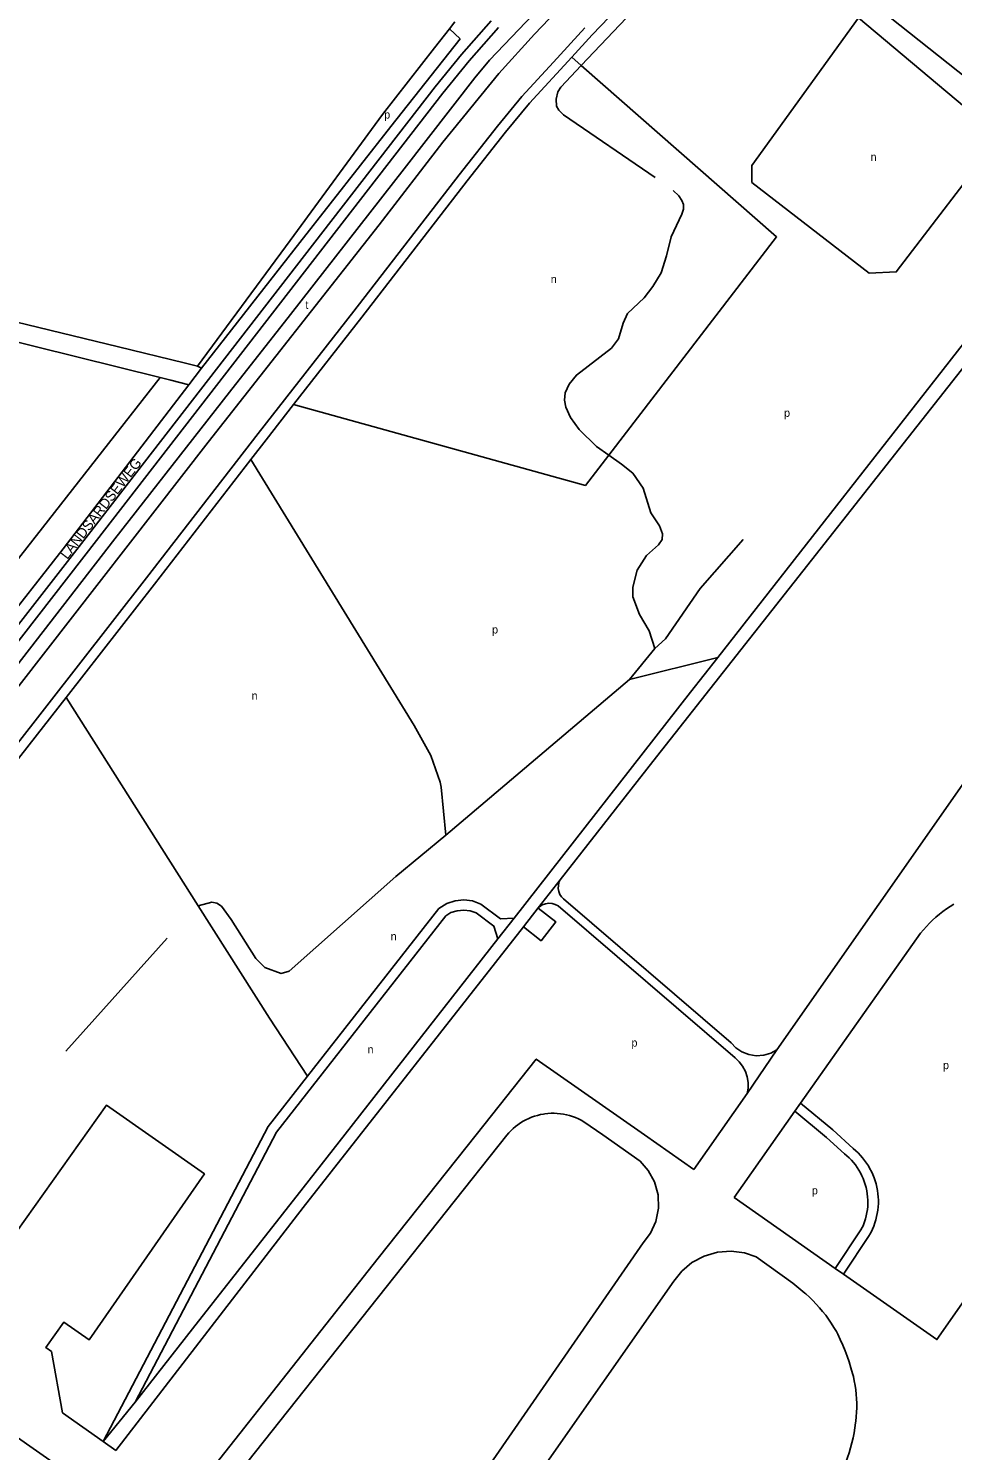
# Model space of a CAD drawing. Extents: x 153608 to 155459, y 385052 to 386919.
# Drawn here: x 154363 to 154825, y 385542 to 386253 of the extents above; entities that cross this region are included whole.
import ezdxf

# ---------------------------------------------------------------- set-up
doc = ezdxf.new("R2010")
doc.units = 0
for name, color, linetype in [('BLT_Basislijn', 7, 'Continuous'), ('BLT_Centroide', 7, 'Continuous'), ('BLT_Gemeentegrens', 7, 'Continuous'), ('BLT_Straatnaam', 7, 'Continuous'), ('BLT_Vlakafsluiter', 7, 'Continuous')]:
    doc.layers.add(name, color=color, linetype=linetype)

msp = doc.modelspace()

# ---------------------------------------------------------------- linework, layer by layer
at = {"layer": 'BLT_Basislijn'}
for p, q in [((154573.02, 386252.97), (154578.48, 386248.02)), ((154638.96, 386234.72), (154634.18, 386238.92)), ((154674.74, 385886.78), (154837.72, 386093.56)), ((154343.74, 385970.46), (154428.43, 386078.64)), ((154428.43, 386078.64), (154433.8, 386077.3)), ((154433.8, 386077.3), (154442.81, 386075.07)), ((154380, 385993.06), (154333.96, 385934.36)), ((154663.15, 385927.63), (154675.74, 385943.15)), ((154663.15, 385927.63), (154707.16, 385938.62)), ((154693.63, 385921.31), (154707.16, 385938.62)), ((154571.22, 385849.81), (154663.15, 385927.63)), ((154605.36, 385808.4), (154693.63, 385921.31)), ((154381.51, 385918.75), (154447.56, 385814.53)), ((154628.36, 385827.58), (154674.74, 385886.78)), ((154617.38, 385813.47), (154628.36, 385827.58)), ((154715.87, 385738.47), (154627.35, 385814.5)), ((154713.81, 385746.01), (154630.12, 385817.98)), ((154610.04, 385804.1), (154617.38, 385813.47)), ((154617.44, 385813.43), (154617.38, 385813.47)), ((154500, 385663.66), (154610.04, 385804.1)), ((154808.52, 385800.91), (154748.61, 385715.92)), ((154431.99, 385798.35), (154381.41, 385741.83)), ((154520.98, 385700.47), (154597.23, 385798.01)), ((154736.7, 385742.49), (154721.86, 385720.64)), ((154721.86, 385720.64), (154695.27, 385682.74)), ((154748.61, 385715.92), (154745.72, 385711.82)), ((154748.61, 385715.92), (154764.75, 385702.49)), ((154745.72, 385711.82), (154715.32, 385668.7)), ((154745.72, 385711.82), (154761.55, 385698.65)), ((154774.87, 385693.18), (154764.75, 385702.49)), ((154500, 385673.64), (154520.98, 385700.47)), ((154541.49, 385623.9), (154601.84, 385699.97)), ((154770.53, 385690.61), (154761.55, 385698.65)), ((154765.91, 385633.26), (154715.32, 385668.7)), ((154406.39, 385542.21), (154500, 385663.66)), ((154778.73, 385652.5), (154765.91, 385633.26)), ((154780, 385654.96), (154778.73, 385652.5)), ((154669.97, 385645.98), (154558.38, 385484.76)), ((154782.89, 385649.72), (154770, 385630.39)), ((154537.42, 385638.43), (154441.78, 385517.22)), ((154770, 385630.39), (154765.91, 385633.26)), ((154685.3, 385626.86), (154450.13, 385291.98)), ((154541.49, 385623.9), (154451.39, 385510.44)), ((154406.39, 385542.21), (154399.99, 385546.73))]:
    msp.add_line(p, q, dxfattribs=at)
for points in [[(155118.98, 386516.32), (155043.31, 386507.56), (154984.44, 386500.69), (154957.8, 386497.87), (154935.67, 386494.66), (154921.56, 386492.19), (154909.21, 386489.15), (154900.34, 386486.13), (154887.57, 386481.19), (154872.57, 386474.02), (154860.57, 386467.01), (154848.91, 386458.9), (154837.63, 386449.86), (154823.59, 386436.18), (154773.02, 386383.56), (154708.26, 386316.53), (154644.42, 386250.05)], [(154638.96, 386234.72), (154832.16, 386438.21), (154847.77, 386451.8), (154859, 386460.09), (154874.32, 386469.26), (154889.64, 386476.88), (154906.27, 386482.72), (154923.43, 386487.36), (154945.45, 386491.33), (154963.11, 386493.79), (155009.53, 386499.23)], [(154745.51, 386395.94), (154651.35, 386298.5), (154593.06, 386237.32), (154585.71, 386228.52), (154550.39, 386183.09), (154493.67, 386110.22), (154463.08, 386071.36), (154405.83, 385998.1), (154327.19, 385896.61), (154289.38, 385847.11), (154273.88, 385824), (154259.18, 385798.01), (154218.87, 385726.19), (154202.46, 385696.25), (154159, 385622.99), (154144.16, 385603.56), (154139.31, 385598.7), (154138.16, 385595.98)], [(154754.37, 386395.71), (154615.6, 386250.29), (154597.76, 386230.66), (154569.71, 386196.31), (154538.03, 386154.95), (154452.53, 386046.43), (154357.94, 385924.71), (154293.71, 385841.85), (154282.27, 385823.81), (154269.07, 385801.81), (154202.93, 385683.02), (154166.56, 385620.26), (154155.85, 385605), (154148.23, 385596.21), (154143.53, 385591.51), (154141.05, 385591.43)], [(154341.17, 385934.15), (154392.73, 386000.27), (154500.64, 386139.76), (154565.87, 386224.01), (154579.08, 386240.21), (154593.88, 386257.02)], [(154640.74, 386253.44), (154625.05, 386236.37), (154609.33, 386219.18), (154597.17, 386204.41), (154577.98, 386180.02), (154525.27, 386111.88), (154477.44, 386050.65), (154421.65, 385978.46), (154354.9, 385892.7), (154310.03, 385834.83), (154295.19, 385813.79), (154283.1, 385794.92), (154259.28, 385752.24)], [(154597.57, 386253.65), (154582.89, 386236.98), (154569.79, 386220.89), (154504.59, 386136.7), (154396.67, 385997.21), (154345.11, 385931.07)], [(154578.48, 386248.02), (154543.86, 386204.2), (154498.24, 386146.17)], [(154644.42, 386250.05), (154634.18, 386238.92)], [(154634.18, 386238.92), (154613.1, 386215.91), (154601.06, 386201.28), (154581.92, 386176.95), (154529.22, 386108.82), (154495.11, 386065.15)], [(154675.94, 386178.69), (154630.03, 386209.94), (154627.74, 386212.34), (154626.64, 386214.42), (154626.35, 386217.82), (154627.23, 386221.57), (154628.71, 386223.92), (154638.96, 386234.72)], [(154652.72, 386039.91), (154736.56, 386149), (154638.96, 386234.72)], [(154060.93, 386169.83), (154073.68, 386166.67), (154428.43, 386078.64)], [(154652.72, 386039.91), (154646.62, 386044.25), (154637.92, 386052.75), (154633.65, 386058.74), (154631.19, 386063.81), (154630.56, 386067.39), (154630.92, 386071), (154632.99, 386075.31), (154636.57, 386079.89), (154654, 386093.3), (154657.53, 386097.95), (154659.84, 386105.92), (154662.07, 386110.75), (154670.46, 386118.5), (154674.81, 386124.16), (154678.94, 386131.05), (154681.52, 386139.5), (154683.87, 386149.01), (154689.19, 386160.29), (154689.98, 386162.89), (154690.06, 386165.11), (154689.23, 386167.18), (154687.7, 386169.56), (154684.83, 386172.21)], [(154707.16, 385938.62), (154835.97, 386103.38), (154838.35, 386105.66), (154840.9, 386108.05), (154844.93, 386110.45), (154847.62, 386111.79), (154850.16, 386113.89), (154852.4, 386116.73), (154853.9, 386120.32), (154854.2, 386123.31), (154854.2, 386127.49), (154853.15, 386134.07), (154852.4, 386140.21), (154851.96, 386144.84), (154851.81, 386148.88), (154851.96, 386152.17), (154852.7, 386156.36), (154854.35, 386160.54), (154856.63, 386164.91)], [(154498.24, 386146.17), (154449.15, 386083.43)], [(154449.15, 386083.43), (154447.21, 386084.35)], [(154442.81, 386075.07), (154380, 385993.06)], [(154495.11, 386065.15), (154481.39, 386047.58), (154473.79, 386037.75)], [(154495.11, 386065.15), (154641.03, 386024.7), (154652.72, 386039.91)], [(154473.79, 386037.75), (154425.6, 385975.39), (154381.51, 385918.75)], [(154473.79, 386037.75), (154555.51, 385904.76), (154563.8, 385889.74), (154568.46, 385876.32), (154568.88, 385873.95), (154571.22, 385849.81)], [(154675.74, 385943.15), (154672.89, 385952.08), (154668.14, 385960.16), (154664.73, 385969.03), (154664.75, 385973.89), (154666.93, 385982.32), (154671.5, 385989.74), (154677.64, 385995.01), (154679.35, 385997.75), (154679.55, 386000.53), (154678.01, 386004.56), (154673.77, 386011.09), (154669.86, 386023.4), (154664.73, 386030.84), (154659.05, 386035.42), (154652.72, 386039.91)], [(154675.74, 385943.15), (154681.13, 385948.03), (154698.37, 385973.2), (154719.87, 385997.69)], [(154381.51, 385918.75), (154358.84, 385889.63), (154314.05, 385831.86), (154299.34, 385811), (154287.39, 385792.35), (154263.62, 385749.77)], [(154840.32, 385887.12), (154838.7, 385888.27), (154736.7, 385742.49)], [(154571.22, 385849.81), (154546.25, 385829.28), (154492.88, 385781.87), (154488.91, 385780.74), (154480.81, 385783.67), (154476.25, 385788.21), (154463.92, 385807.76), (154459.06, 385814.45), (154456.87, 385815.92), (154454.29, 385816.41), (154447.56, 385814.53)], [(154628.36, 385827.58), (154627.81, 385826.26), (154627.51, 385824.79), (154627.48, 385823.25), (154627.76, 385821.72), (154628.33, 385820.29), (154629.14, 385819.02), (154630.12, 385817.98)], [(154447.56, 385814.53), (154483.1, 385758.46), (154502.13, 385729.32)], [(154502.13, 385729.32), (154567.84, 385813.22), (154571.69, 385815.75), (154575.93, 385817.05), (154580.24, 385817.47), (154584.63, 385817.02), (154588.84, 385815.41), (154598.66, 385808.11), (154605.36, 385808.4)], [(154627.35, 385814.5), (154626, 385815.24), (154624.44, 385815.71), (154622.76, 385815.84), (154621.08, 385815.6), (154619.5, 385815.01), (154618.14, 385814.12), (154617.44, 385813.43)], [(154808.52, 385800.91), (154809.95, 385802.61), (154811.44, 385804.27), (154812.98, 385805.86), (154814.58, 385807.41), (154816.24, 385808.89), (154817.95, 385810.31), (154819.71, 385811.67), (154821.51, 385812.97), (154823.36, 385814.2), (154825.26, 385815.36)], [(154415.94, 385566.41), (154486.65, 385701.44), (154571.27, 385809.49), (154573.83, 385811.18), (154576.92, 385812.12), (154580.23, 385812.45), (154583.46, 385812.11), (154586.41, 385810.99), (154595.25, 385804.41), (154597.23, 385798.01)], [(154610.04, 385804.1), (154618.89, 385797.11), (154626.28, 385806.5), (154617.44, 385813.43)], [(154736.7, 385742.49), (154733.68, 385740.87), (154730.2, 385739.85), (154726.46, 385739.59), (154722.7, 385740.17), (154719.21, 385741.55), (154716.2, 385743.56), (154713.81, 385746.01)], [(154695.27, 385682.74), (154670.64, 385700), (154616.5, 385737.89), (154586.45, 385700), (154537.42, 385638.43)], [(154715.87, 385738.47), (154717.88, 385736.6), (154719.61, 385734.36), (154720.98, 385731.8), (154721.91, 385729.04), (154722.36, 385726.18), (154722.33, 385723.34), (154721.86, 385720.64)], [(154399.99, 385546.73), (154482.43, 385704.16), (154502.13, 385729.32)], [(154399.99, 385546.73), (154379.63, 385561.1), (154374.24, 385591.68), (154371.37, 385593.71), (154380.3, 385606.38), (154392.94, 385597.52), (154450.59, 385680.49), (154401.66, 385714.83), (154343.04, 385632.56), (154355.71, 385623.64), (154346.8, 385610.92), (154282.5, 385655.99), (154251.78, 385650.69), (154235.63, 385661.35), (154222.76, 385642.9), (154386.19, 385528.38)], [(154901.88, 385719.14), (154900, 385716.45), (154888.39, 385700), (154816.71, 385597.68), (154770, 385630.39)], [(154620.09, 385710.46), (154618.57, 385710.17), (154617.06, 385709.8), (154615.58, 385709.35), (154614.12, 385708.83), (154612.69, 385708.23), (154611.29, 385707.55), (154609.93, 385706.81), (154608.61, 385706), (154607.33, 385705.12), (154606.1, 385704.18), (154604.92, 385703.17), (154603.79, 385702.1), (154602.72, 385700.98), (154601.84, 385699.97)], [(154640.31, 385706.63), (154638.95, 385707.39), (154637.54, 385708.07), (154636.1, 385708.68), (154634.64, 385709.22), (154633.14, 385709.69), (154631.63, 385710.07), (154630.1, 385710.38), (154628.55, 385710.61), (154627, 385710.76), (154625.43, 385710.83), (154623.87, 385710.82), (154622.31, 385710.73), (154620.76, 385710.56), (154620.09, 385710.46)], [(154640.31, 385706.63), (154649.73, 385700), (154668.41, 385686.85)], [(154668.41, 385686.85), (154672.41, 385682.28), (154675.51, 385676.62), (154677.33, 385670.14), (154677.59, 385663.32), (154676.27, 385656.72), (154673.61, 385650.83), (154669.97, 385645.98)], [(154770.53, 385690.61), (154771.74, 385689.6), (154772.89, 385688.53), (154773.99, 385687.4), (154775.02, 385686.22), (154776, 385684.98), (154776.91, 385683.7), (154777.76, 385682.37), (154778.54, 385681), (154779.24, 385679.6), (154779.88, 385678.16), (154780.43, 385676.69), (154780.92, 385675.19), (154781.33, 385673.67), (154781.66, 385672.13), (154781.91, 385670.58), (154782.08, 385669.01), (154782.18, 385667.44), (154782.19, 385665.87), (154782.12, 385664.29), (154781.97, 385662.73), (154781.75, 385661.17), (154781.44, 385659.62), (154781.06, 385658.1), (154780.6, 385656.59), (154780.06, 385655.11), (154780, 385654.96)], [(154774.87, 385693.18), (154776.12, 385692.12), (154777.33, 385690.99), (154778.47, 385689.8), (154779.56, 385688.57), (154780.59, 385687.28), (154781.55, 385685.94), (154782.45, 385684.55), (154783.27, 385683.13), (154784.03, 385681.66), (154784.72, 385680.16), (154785.33, 385678.63), (154785.87, 385677.08), (154786.33, 385675.49), (154786.71, 385673.89), (154787.02, 385672.27), (154787.25, 385670.64), (154787.4, 385668.99), (154787.46, 385667.35), (154787.45, 385665.7), (154787.36, 385664.05), (154787.19, 385662.41), (154786.94, 385660.78), (154786.61, 385659.17), (154786.2, 385657.57), (154785.72, 385655.99), (154785.15, 385654.44), (154784.52, 385652.92), (154783.81, 385651.43), (154783.03, 385649.98), (154782.89, 385649.72)], [(154415.94, 385566.41), (154444.68, 385603.1), (154500, 385673.64)], [(154726.46, 385638.98), (154720.49, 385641.04), (154713.88, 385641.92), (154707.01, 385641.41), (154700.33, 385639.44), (154694.28, 385636.15), (154689.21, 385631.83), (154685.3, 385626.86)], [(154750.73, 385620.95), (154744.69, 385625.91), (154726.46, 385638.98)], [(154766.51, 385601.68), (154765.27, 385603.78), (154763.95, 385605.84), (154762.58, 385607.86), (154761.13, 385609.82), (154759.62, 385611.74), (154758.05, 385613.61), (154756.42, 385615.43), (154754.73, 385617.19), (154752.99, 385618.9), (154751.19, 385620.55), (154750.73, 385620.95)], [(154774.58, 385580.76), (154773.75, 385583.64), (154772.84, 385586.49), (154771.85, 385589.32), (154770.79, 385592.13), (154769.66, 385594.9), (154768.45, 385597.65), (154767.17, 385600.36), (154766.51, 385601.68)], [(154776.15, 385556.86), (154776.39, 385559.1), (154776.55, 385561.35), (154776.63, 385563.6), (154776.63, 385565.85), (154776.55, 385568.1), (154776.39, 385570.34), (154776.15, 385572.58), (154775.83, 385574.81), (154775.44, 385577.02), (154774.96, 385579.22), (154774.58, 385580.76)], [(154770.17, 385533.93), (154771.13, 385536.3), (154772.02, 385538.7), (154772.83, 385541.13), (154773.57, 385543.58), (154774.22, 385546.06), (154774.8, 385548.55), (154775.3, 385551.06), (154775.73, 385553.58), (154776.07, 385556.12), (154776.15, 385556.86)]]:
    msp.add_lwpolyline(points, dxfattribs=at)
for points in [[(154856.58, 386359.27), (154783.71, 386266.32), (154856.11, 386208.79), (154924.13, 386301.7)], [(154777.49, 386258.49), (154724.3, 386184.63), (154724.27, 386176.18), (154782.89, 386130.91), (154796.43, 386131.44), (154848.23, 386199.21)]]:
    msp.add_lwpolyline(points, close=True, dxfattribs=at)
at = {"layer": 'BLT_Gemeentegrens'}
for p, q in [((154573.02, 386252.97), (154575.73, 386256.44)), ((154440.56, 386085.97), (154447.21, 386084.35))]:
    msp.add_line(p, q, dxfattribs=at)
for points in [[(154539.69, 386210.13), (154565.65, 386243.49), (154573.02, 386252.97)], [(154447.21, 386084.35), (154493.45, 386147.24), (154539.69, 386210.13)], [(154281.95, 386124.59), (154407.66, 386093.98), (154440.56, 386085.97)]]:
    msp.add_lwpolyline(points, dxfattribs=at)
at = {"layer": 'BLT_Vlakafsluiter'}
for p, q in [((154442.81, 386075.07), (154449.15, 386083.43)), ((154597.23, 385798.01), (154605.36, 385808.4)), ((154399.99, 385546.73), (154415.94, 385566.41))]:
    msp.add_line(p, q, dxfattribs=at)

# ---------------------------------------------------------------- texts
at = {"layer": 'BLT_Centroide'}
for s, p in [('p', (154540.46, 386208.14)), ('n', (154783.58, 386186.97)), ('n', (154623.72, 386125.89)), ('t', (154501.07, 386113.02)), ('p', (154740.34, 386059.03)), ('p', (154594.4, 385950.69)), ('n', (154474.16, 385917.64)), ('n', (154543.71, 385797.32)), ('n', (154532.13, 385740.78)), ('p', (154664.06, 385744.17)), ('p', (154819.79, 385732.9)), ('p', (154754.24, 385670.27))]:
    msp.add_text(s, height=4, dxfattribs=at).set_placement(p)
at = {"layer": 'BLT_Straatnaam'}
msp.add_text('LANDSARDSEWEG', height=5, rotation=52.27395, dxfattribs=at).set_placement((154382.05, 385987.43))

doc.saveas('drawing.dxf')
